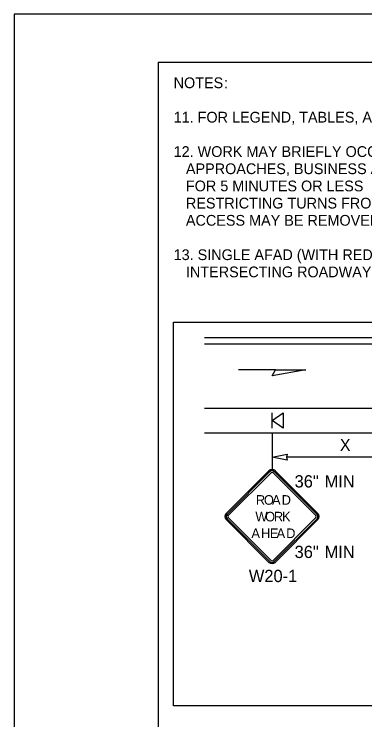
# Model space of a CAD drawing. Extents: x 99999.1 to 100095.7, y 99995 to 100010.7.
# Drawn here: x 100019.062 to 100021.344, y 100006.089 to 100010.687 of the extents above; entities that cross this region are included whole.
import ezdxf

# ---------------------------------------------------------------- set-up
doc = ezdxf.new("R2010")
doc.units = 0
for name, color, linetype in [('RD_ED_ShoulderPavedEdge', 7, 'Continuous'), ('RD_MK_LineDblYellowCenter', 7, 'Continuous'), ('RD_MK_LineEdgeWhite', 7, 'Continuous'), ('SH_GI_GeneralNotesBodyText', 7, 'Continuous'), ('SH_GI_PlotLimits', 7, 'Continuous'), ('SH_GI_SheetBorder', 7, 'Continuous'), ('TR_SN_ConstructionSigns', 7, 'Continuous'), ('TR_WZ_PortableSignMountBlk-Org', 7, 'Continuous'), ('TR_WZ_WorkZoneDetails', 7, 'Continuous'), ('TR_WZ_WorkZoneTextCurrent', 7, 'Continuous')]:
    doc.layers.add(name, color=color, linetype=linetype)

msp = doc.modelspace()

# ---------------------------------------------------------------- linework, layer by layer
at = {"layer": 'RD_ED_ShoulderPavedEdge'}
msp.add_line((100020.3, 100007.9602), (100024.9804, 100007.9602), dxfattribs=at)
at = {"layer": 'RD_MK_LineDblYellowCenter'}
for p, q in [((100020.3, 100008.5802), (100023.7402, 100008.5802)), ((100020.3, 100008.5402), (100023.7402, 100008.5402))]:
    msp.add_line(p, q, dxfattribs=at)
at = {"layer": 'RD_MK_LineEdgeWhite'}
msp.add_line((100020.3, 100008.1202), (100024.9804, 100008.1202), dxfattribs=at)
at = {"layer": 'SH_GI_PlotLimits'}
msp.add_lwpolyline([(100019.0625, 99999.6875), (100036.0625, 99999.6875), (100036.0625, 100010.6875), (100019.0625, 100010.6875)], close=True, dxfattribs=at)
at = {"layer": 'SH_GI_SheetBorder'}
for q in [(100020, 100000), (100035.75, 100010.375)]:
    msp.add_line((100020, 100010.375), q, dxfattribs=at)
at = {"layer": 'TR_SN_ConstructionSigns'}
for p, q in [((100020.7203, 100007.712), (100020.4419, 100007.4336)), ((100020.7258, 100007.7065), (100020.4474, 100007.428)), ((100020.4551, 100007.4203), (100020.7335, 100007.6987)), ((100020.7468, 100007.6987), (100021.0252, 100007.4203)), ((100021.0329, 100007.428), (100020.7545, 100007.7065)), ((100021.0385, 100007.4336), (100020.76, 100007.712)), ((100020.4474, 100007.3993), (100020.7258, 100007.1209)), ((100020.7335, 100007.1286), (100020.4551, 100007.4071)), ((100021.0252, 100007.4071), (100020.7468, 100007.1286)), ((100020.7545, 100007.1209), (100021.0329, 100007.3993)), ((100020.4419, 100007.3938), (100020.7203, 100007.1154)), ((100020.76, 100007.1154), (100021.0385, 100007.3938))]:
    msp.add_line(p, q, dxfattribs=at)
for centre, radius, start, end in [((100020.7402, 100007.6921), 0.0281, 45, 135), ((100020.7402, 100007.6921), 0.0203, 45, 135), ((100020.7402, 100007.6921), 0.00937, 45, 135), ((100020.4617, 100007.4137), 0.0281, 135, 225), ((100020.4617, 100007.4137), 0.0203, 135, 225), ((100020.4617, 100007.4137), 0.00937, 135, 225), ((100021.0186, 100007.4137), 0.00937, 315, 45), ((100021.0186, 100007.4137), 0.0203, 315, 45), ((100021.0186, 100007.4137), 0.0281, 315, 45), ((100020.7402, 100007.1353), 0.0203, 225, 315), ((100020.7402, 100007.1353), 0.00937, 225, 315), ((100020.7402, 100007.1353), 0.0281, 225, 315)]:
    msp.add_arc(centre, radius, start, end, dxfattribs=at)
at = {"layer": 'TR_WZ_PortableSignMountBlk-Org'}
msp.add_line((100020.7402, 100007.9902), (100020.7402, 100008.0902), dxfattribs=at)
msp.add_lwpolyline([(100020.7402, 100008.0401), (100020.812, 100008.0902), (100020.812, 100007.9902)], close=True, dxfattribs=at)
at = {"layer": 'TR_WZ_WorkZoneDetails'}
for p, q in [((100020.7624, 100008.3695), (100020.5213, 100008.3695)), ((100020.7402, 100007.9605), (100020.7402, 100007.7202)), ((100021.5964, 100007.8002), (100020.8339, 100007.8002))]:
    msp.add_line(p, q, dxfattribs=at)
for points in [[(100020.959, 100008.3695), (100020.7402, 100008.3309), (100020.7624, 100008.3695)], [(100020.7402, 100007.8002), (100020.8384, 100007.8195), (100020.8339, 100007.8002), (100020.8384, 100007.781)]]:
    msp.add_lwpolyline(points, close=True, dxfattribs=at)
at = {"layer": 'TR_WZ_WorkZoneTextCurrent'}
msp.add_lwpolyline([(100020.1, 100008.6802), (100025.15, 100008.6802), (100025.15, 100006.1804), (100020.1, 100006.1804)], close=True, dxfattribs=at)

# ---------------------------------------------------------------- texts
at = {"layer": 'SH_GI_GeneralNotesBodyText'}
for s, p in [('NOTES', (100020.1, 100010.205)), (':', (100020.4275, 100010.205)), ('11. FOR LEGEND, TABLES, AND ADDITIONAL NOTES: SEE TC430, SHEET 1.', (100020.1, 100009.981)), ('12. WORK MAY BRIEFLY OCCUR WITHIN LANE CLOSURE ACROSS INTERSECTING ROADWAY ', (100020.1, 100009.757)), ('APPROACHES, BUSINESS ACCESSES, OR DRIVEWAYS. ', (100020.18, 100009.645)), ('FOR 5 MINUTES OR LESS', (100020.18, 100009.533)), ('RESTRICTING TURNS FROM MAINLINE. CHANNELIZATION DEVICES DELINEATING APPROACH OR ', (100020.18, 100009.421)), ('ACCESS MAY BE REMOVED OR RELOCATED AS NEEDED.', (100020.18, 100009.309)), ('13. SINGLE AFAD (WITH RED FLAG/ RED GLOW CONE FLASHLIGHT) MAY BE ADDED TO THE ', (100020.1, 100009.085)), ('INTERSECTING ROADWAY APPROACH TO HELP GUIDE ALTERNATING & TURNING TRAFFIC.', (100020.18, 100008.973))]:
    msp.add_text(s, height=0.07, rotation=360, dxfattribs=at).set_placement(p)
at = {"layer": 'TR_SN_ConstructionSigns'}
for s, p in [('36"', (100020.8869, 100007.6035)), ('MIN', (100021.0819, 100007.6035)), ('36"', (100020.8869, 100007.1439)), ('MIN', (100021.0819, 100007.1439)), ('W20-1', (100020.5892, 100006.9871))]:
    msp.add_text(s, height=0.08, rotation=360, dxfattribs=at).set_placement(p)
for s, p in [('R', (100020.6351, 100007.491)), ('O', (100020.6872, 100007.491)), ('A', (100020.74, 100007.491)), ('D', (100020.8027, 100007.491)), ('W', (100020.6318, 100007.3824)), ('O', (100020.6951, 100007.3824)), ('R', (100020.7523, 100007.3824)), ('K', (100020.8047, 100007.3824)), ('A', (100020.6058, 100007.2739)), ('H', (100020.6683, 100007.2739)), ('E', (100020.7258, 100007.2739)), ('A', (100020.7695, 100007.2739)), ('D', (100020.832, 100007.2739))]:
    msp.add_text(s, height=0.0625, dxfattribs=at).set_placement(p)
at = {"layer": 'TR_WZ_WorkZoneTextCurrent'}
msp.add_text('X', height=0.08, rotation=360, dxfattribs=at).set_placement((100021.1804, 100007.8402))

doc.saveas('drawing.dxf')
